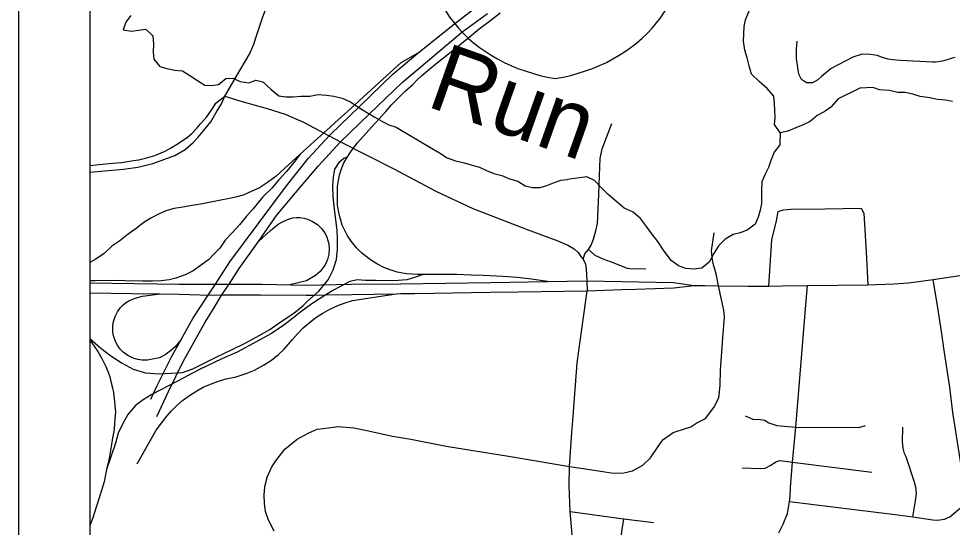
# Model space of a CAD drawing. Extents: x 0 to 34, y 0 to 22.
# Drawn here: x 12.665 to 13.978, y 5.441 to 6.155 of the extents above; entities that cross this region are included whole.
import ezdxf

# ---------------------------------------------------------------- set-up
doc = ezdxf.new("R2010")
doc.units = 0
for name, color, linetype in [('GM_X_City_Street', 7, 'Continuous'), ('GM_X_Corporation', 7, 'Continuous'), ('GM_X_Interchange_Ramps', 7, 'Continuous'), ('GM_X_Interstate_Route', 7, 'Continuous'), ('GM_X_Interstate_Shield', 7, 'Continuous'), ('GM_X_Minor_River', 7, 'Continuous'), ('GM_X_Minor_River_Text', 7, 'Continuous'), ('GM_X_State_Route', 7, 'Continuous'), ('GM_X_US_Route', 7, 'Continuous'), ('SH_Data', 7, 'Continuous')]:
    doc.layers.add(name, color=color, linetype=linetype)

msp = doc.modelspace()

# ---------------------------------------------------------------- linework, layer by layer
at = {"layer": 'GM_X_City_Street'}
msp.add_line((13.7534, 5.5325), (13.8647, 5.5184), dxfattribs=at)
for points in [[(12.9544, 6.0468), (12.9755, 6.0825), (12.9848, 6.0975), (12.9892, 6.1054), (12.9954, 6.1197), (12.9993, 6.1316), (13.0074, 6.1566), (13.0238, 6.2011)], [(13.9819, 6.1008), (13.9778, 6.0999), (13.9659, 6.0963), (13.9586, 6.0949), (13.9544, 6.0945), (13.9505, 6.0945), (13.9046, 6.0969), (13.8939, 6.0976), (13.8878, 6.0985), (13.88, 6.1011), (13.8725, 6.1038), (13.8594, 6.1058), (13.8497, 6.1051), (13.8381, 6.1012), (13.8077, 6.0855), (13.7939, 6.0744), (13.7887, 6.0696), (13.7814, 6.0654), (13.773, 6.0655), (13.7658, 6.0699), (13.7619, 6.0774), (13.7588, 6.0994), (13.7589, 6.1127), (13.7596, 6.124)], [(12.7646, 5.9396), (12.7806, 5.9413), (12.8123, 5.944), (12.8321, 5.947), (12.8534, 5.9518), (12.8704, 5.958), (12.8842, 5.9634), (12.8986, 5.9718), (12.9103, 5.9814), (12.9173, 5.989), (12.9264, 6.0002), (12.9348, 6.0103), (12.9425, 6.0235), (12.9498, 6.0358), (12.9544, 6.0468)], [(12.7646, 5.9492), (12.7913, 5.952), (12.8093, 5.9536), (12.8232, 5.9555), (12.8333, 5.9573), (12.843, 5.9593), (12.8561, 5.9634), (12.8706, 5.9694), (12.8781, 5.9734), (12.8891, 5.98), (12.902, 5.9891), (12.908, 5.9942), (12.9158, 6.0022), (12.9206, 6.0076), (12.9287, 6.0172), (12.9376, 6.0296), (12.9418, 6.0367), (12.9544, 6.0468)], [(12.9544, 6.0468), (12.9771, 6.0397), (13.0144, 6.0293), (13.0396, 6.0211), (13.0653, 6.0099), (13.1012, 5.9909), (13.1101, 5.9861)], [(13.4586, 5.8177), (13.4612, 5.8249), (13.4663, 5.8313), (13.4702, 5.8372), (13.4716, 5.8411), (13.4734, 5.8457), (13.4763, 5.8573), (13.4791, 5.8676), (13.4808, 5.9085), (13.4816, 5.9346), (13.4824, 5.959), (13.4853, 5.9727), (13.494, 5.9946), (13.499, 6.0082)], [(13.1101, 5.9861), (13.1172, 5.9824), (13.1925, 5.9443), (13.2516, 5.9132), (13.3034, 5.8888), (13.3801, 5.8593), (13.4229, 5.8435), (13.4372, 5.8374), (13.4462, 5.8323), (13.4515, 5.827), (13.4556, 5.8215)], [(13.7199, 5.7798), (13.7218, 5.8085), (13.7242, 5.8445), (13.7305, 5.8712), (13.7328, 5.8845), (13.7407, 5.8869), (13.7508, 5.8877), (13.7987, 5.8884), (13.8496, 5.8892), (13.8537, 5.882), (13.8569, 5.8276), (13.8592, 5.7817)], [(13.6492, 5.7803), (13.6461, 5.7946), (13.6437, 5.8036), (13.6415, 5.8115), (13.64, 5.82), (13.6392, 5.8294), (13.6429, 5.8546)], [(13.4556, 5.8215), (13.4586, 5.8177), (13.4618, 5.8103), (13.4629, 5.8037), (13.464, 5.787), (13.4643, 5.7732)], [(13.4663, 5.8313), (13.4749, 5.8231), (13.4863, 5.8178), (13.5018, 5.8122), (13.5167, 5.8062), (13.52, 5.8047), (13.5243, 5.8044), (13.547, 5.8039)], [(13.4397, 5.526), (13.4683, 5.5221), (13.489, 5.5189), (13.5012, 5.5168), (13.5159, 5.5172), (13.5283, 5.5202), (13.5428, 5.5283), (13.5534, 5.5386), (13.5635, 5.5529), (13.5706, 5.5639), (13.5855, 5.574), (13.6027, 5.5795), (13.6104, 5.582), (13.6188, 5.5876), (13.6309, 5.5936), (13.6427, 5.6093), (13.6497, 5.6227), (13.6513, 5.6399), (13.6521, 5.6619), (13.6537, 5.687), (13.6553, 5.7068), (13.6573, 5.7359), (13.6566, 5.7459), (13.6492, 5.7803)], [(13.7338, 5.4329), (13.7401, 5.4451), (13.7463, 5.4604), (13.7491, 5.4768), (13.7499, 5.4839), (13.7503, 5.4968), (13.7534, 5.5325), (13.7577, 5.5815), (13.772, 5.7536), (13.7745, 5.7807)], [(14.0102, 5.4958), (14.002, 5.5019), (13.9972, 5.5071), (13.9938, 5.5119), (13.9918, 5.5187), (13.9787, 5.6019), (13.9745, 5.6379), (13.9663, 5.6927), (13.9636, 5.71), (13.9579, 5.7464), (13.9511, 5.7888)], [(13.4451, 5.6022), (13.4451, 5.6032), (13.4501, 5.6721), (13.4643, 5.7732)], [(13.5638, 4.8429), (13.5518, 4.9196), (13.5394, 5.0228), (13.5335, 5.0511), (13.5283, 5.0648), (13.5128, 5.1064), (13.4939, 5.1627), (13.4835, 5.1909), (13.4739, 5.2251), (13.4632, 5.2698), (13.4577, 5.3026), (13.455, 5.3174), (13.4484, 5.3746), (13.4454, 5.4039), (13.4405, 5.463), (13.4391, 5.4994), (13.4397, 5.526), (13.4427, 5.5741), (13.4451, 5.6022)], [(13.6868, 5.5976), (13.6974, 5.5925), (13.7083, 5.5921), (13.7138, 5.5913), (13.7197, 5.5878), (13.7311, 5.5838), (13.7577, 5.5815)], [(13.0138, 5.5104), (13.0207, 5.5258), (13.0264, 5.534), (13.039, 5.5508), (13.0562, 5.5647), (13.0717, 5.5729), (13.0844, 5.5786), (13.1003, 5.5806), (13.1142, 5.5822), (13.1359, 5.5806), (13.1542, 5.5769), (13.1906, 5.5688), (13.2165, 5.5644), (13.2662, 5.5548), (13.3539, 5.5409), (13.3926, 5.534), (13.4397, 5.526)], [(13.7577, 5.5815), (13.8463, 5.5811), (13.8557, 5.5838)], [(13.9226, 5.4553), (13.9264, 5.4779), (13.9274, 5.4882), (13.9267, 5.4971), (13.9246, 5.504), (13.9133, 5.5397), (13.9109, 5.5443), (13.909, 5.5521), (13.9078, 5.5611), (13.9082, 5.5815)], [(13.6825, 5.5243), (13.7075, 5.5235), (13.7146, 5.5239), (13.722, 5.5278), (13.7307, 5.5333), (13.7358, 5.5345), (13.7534, 5.5325)], [(13.7491, 5.4768), (13.9014, 5.4584), (13.9226, 5.4553), (13.9507, 5.4512), (13.9572, 5.4509), (13.9671, 5.4523), (13.9743, 5.4557), (13.9805, 5.4608), (13.9928, 5.4708), (14.0003, 5.4786), (14.0102, 5.4958), (14.0167, 5.5084), (14.0253, 5.5166), (14.0349, 5.5225), (14.0448, 5.5252), (14.077, 5.5296)], [(13.0138, 5.5104), (13.0103, 5.4977), (13.0094, 5.4858), (13.0101, 5.4744), (13.0116, 5.4633), (13.0154, 5.4515), (13.0235, 5.436)], [(13.4405, 5.463), (13.5158, 5.4526), (13.5575, 5.4477)], [(13.5121, 5.368), (13.5093, 5.3862), (13.509, 5.4028), (13.511, 5.4223), (13.5158, 5.4526)]]:
    msp.add_lwpolyline(points, dxfattribs=at)
at = {"layer": 'GM_X_Corporation'}
for points in [[(12.7646, 9.6504), (12.7646, 4.5526)], [(16.0546, 8.4904), (15.3473, 8.5302), (15.334, 8.5309), (14.9063, 8.5471), (14.6084, 8.5661), (14.4977, 8.5718), (14.2608, 8.5815), (13.795, 8.6047), (13.7169, 8.6042), (13.4613, 8.6292), (13.3525, 8.6386), (13.1948, 8.6507), (13.1161, 8.6564), (13.0467, 8.6615), (12.8988, 8.6726), (12.8448, 8.6761), (12.8296, 8.6783), (12.8119, 8.6756), (12.7953, 8.6676), (12.7646, 8.6719), (12.7646, 3.3841)], [(12.7646, 8.6719), (12.7646, 3.3841)]]:
    msp.add_lwpolyline(points, dxfattribs=at)
at = {"layer": 'GM_X_Interchange_Ramps'}
for points in [[(13.4086, 5.7862), (13.3862, 5.7896), (13.3658, 5.7919), (13.3455, 5.7932), (13.3182, 5.7945), (13.3011, 5.7952), (13.281, 5.7958), (13.2338, 5.7959), (13.2251, 5.7961), (13.21, 5.7968), (13.1972, 5.7994), (13.1857, 5.8031), (13.1784, 5.8057), (13.1692, 5.8103), (13.161, 5.8155), (13.1534, 5.8211), (13.1469, 5.8264), (13.14, 5.8333), (13.1324, 5.8428), (13.1268, 5.8514), (13.1238, 5.857), (13.1199, 5.8655), (13.116, 5.879), (13.1146, 5.8856), (13.1133, 5.8938), (13.113, 5.9037), (13.113, 5.9119), (13.1133, 5.9195), (13.1143, 5.928), (13.116, 5.9362), (13.1186, 5.9444), (13.1222, 5.953), (13.1271, 5.9612), (13.1324, 5.9691), (13.1413, 5.9809), (13.1492, 5.9901), (13.1574, 5.999), (13.1809, 6.0252), (13.1891, 6.0344), (13.1985, 6.0437), (13.209, 6.0539), (13.2189, 6.0631), (13.2251, 6.0694), (13.2317, 6.0756), (13.2402, 6.0826), (13.254, 6.0938), (13.2693, 6.1062), (13.2855, 6.1194), (13.301, 6.1319), (13.3122, 6.1411), (13.3287, 6.1532), (13.3418, 6.1638)], [(13.2259, 6.107), (13.2023, 6.0936), (13.1821, 6.0753), (13.166, 6.0607), (13.149, 6.0452), (13.1265, 6.0248), (13.1146, 6.014), (13.1027, 6.0032), (13.0805, 5.983), (13.0699, 5.9734), (13.0608, 5.9652), (13.0492, 5.9546), (13.0386, 5.945), (13.0267, 5.9342), (13.0148, 5.9254), (13.0035, 5.918), (12.9917, 5.9125), (12.9803, 5.9076), (12.9714, 5.9051), (12.9616, 5.9027), (12.9515, 5.9011), (12.9349, 5.8977), (12.9211, 5.8948), (12.9088, 5.8928), (12.8955, 5.8908), (12.8832, 5.8889), (12.8718, 5.8854), (12.8615, 5.881), (12.8506, 5.8751), (12.8407, 5.8691), (12.8299, 5.8608), (12.8185, 5.8529), (12.8067, 5.8435), (12.7959, 5.8356), (12.785, 5.8257), (12.7732, 5.8174), (12.7646, 5.8129)], [(13.0608, 5.9652), (13.0519, 5.9536), (13.0412, 5.9408), (13.0305, 5.9289), (13.0207, 5.9174), (13.0083, 5.9051), (12.994, 5.8878), (12.9853, 5.8779), (12.9751, 5.866), (12.9648, 5.8545), (12.9553, 5.8442), (12.9475, 5.8331), (12.9397, 5.8249), (12.9315, 5.8167), (12.9216, 5.8097), (12.9101, 5.8011), (12.8986, 5.7953), (12.8859, 5.7908), (12.8764, 5.7887), (12.8653, 5.7871), (12.853, 5.7867), (12.8386, 5.7867), (12.8139, 5.7871), (12.7967, 5.7875), (12.7724, 5.7871), (12.7646, 5.7869)], [(12.7646, 5.7059), (12.7801, 5.6926), (12.7944, 5.6817), (12.8102, 5.6714), (12.8259, 5.663), (12.8432, 5.658), (12.8624, 5.6566), (12.895, 5.6585), (12.9098, 5.6635), (12.931, 5.6743), (12.9443, 5.6807), (12.964, 5.6901), (12.9843, 5.7), (13.003, 5.7103), (13.0178, 5.7187), (13.0326, 5.7291), (13.0518, 5.7419), (13.0642, 5.7518), (13.0711, 5.7587), (13.0869, 5.7725), (13.1002, 5.7887), (13.1071, 5.8026), (13.1115, 5.8169), (13.113, 5.8317), (13.113, 5.845), (13.1125, 5.8583), (13.111, 5.8726), (13.109, 5.8884), (13.1071, 5.9051), (13.1066, 5.9204), (13.1076, 5.9328), (13.1095, 5.9441), (13.1164, 5.955), (13.1219, 5.9594), (13.1271, 5.9612)], [(13.0018, 5.8424), (13.0132, 5.8526), (13.0191, 5.8576), (13.0245, 5.8626), (13.0298, 5.8667), (13.0356, 5.87), (13.043, 5.8733), (13.0503, 5.8756), (13.0553, 5.8761), (13.0603, 5.8759), (13.0662, 5.8751), (13.0721, 5.8734), (13.079, 5.8702), (13.0848, 5.8662), (13.0905, 5.8607), (13.0951, 5.8545), (13.0981, 5.8485), (13.1008, 5.8393), (13.1015, 5.832), (13.1009, 5.8245), (13.0992, 5.8173), (13.0958, 5.8097), (13.0889, 5.8004), (13.0821, 5.7946), (13.0693, 5.7872), (13.0462, 5.7816)], [(13.2338, 5.7959), (13.2215, 5.7917), (13.2106, 5.7887), (13.1983, 5.7878), (13.1825, 5.7873), (13.1668, 5.7878), (13.1524, 5.7878), (13.1411, 5.7883), (13.1303, 5.7863), (13.1066, 5.7735), (13.0839, 5.7596), (13.075, 5.7532), (13.0617, 5.7434), (13.0499, 5.734), (13.0356, 5.7232), (13.0193, 5.7128), (12.9996, 5.7019), (12.9719, 5.6871), (12.9502, 5.6773), (12.9192, 5.6625), (12.8881, 5.6462), (12.8521, 5.6275), (12.8398, 5.6201), (12.8289, 5.6117), (12.8181, 5.5994), (12.8116, 5.5875), (12.8047, 5.5732), (12.8008, 5.5589), (12.788, 5.5222)], [(12.8933, 5.7047), (12.8846, 5.6945), (12.878, 5.6889), (12.8705, 5.6833), (12.8626, 5.679), (12.8527, 5.6769), (12.846, 5.6757), (12.8377, 5.6756), (12.8323, 5.6764), (12.8257, 5.6783), (12.8182, 5.682), (12.8118, 5.6867), (12.8074, 5.6913), (12.804, 5.6959), (12.8007, 5.7019), (12.7983, 5.7086), (12.7972, 5.7147), (12.797, 5.7237), (12.7979, 5.73), (12.8002, 5.7371), (12.8036, 5.7437), (12.8079, 5.7496), (12.8111, 5.7528), (12.8149, 5.756), (12.8198, 5.7592), (12.8284, 5.7629), (12.8386, 5.7655), (12.8494, 5.7671), (12.8636, 5.7687)], [(12.8313, 5.5298), (12.8582, 5.5774), (12.8731, 5.5968), (12.8796, 5.6043), (12.887, 5.6117), (12.8952, 5.6188), (12.9051, 5.6262), (12.9151, 5.6325), (12.9243, 5.6375), (12.9346, 5.6421), (12.9471, 5.6466), (12.9567, 5.6492), (12.9707, 5.6524), (12.9848, 5.6568), (12.9963, 5.6616), (13.0091, 5.6684), (13.0202, 5.6758), (13.0302, 5.6838), (13.0381, 5.6913), (13.0498, 5.7048), (13.0567, 5.7128), (13.0649, 5.721), (13.0762, 5.7306), (13.0841, 5.7364), (13.0924, 5.7417), (13.1024, 5.7472), (13.1138, 5.7524), (13.1224, 5.7556), (13.1343, 5.7594), (13.1955, 5.769)], [(12.7646, 5.7038), (12.7663, 5.7017), (12.7709, 5.6954), (12.7758, 5.6876), (12.782, 5.677), (12.787, 5.6668), (12.7906, 5.6589), (12.7929, 5.652), (12.7949, 5.6438), (12.7968, 5.6366), (12.7978, 5.6303), (12.7991, 5.6218), (12.7998, 5.6126), (12.8008, 5.6027), (12.8001, 5.5935), (12.7995, 5.585), (12.7985, 5.5748), (12.7968, 5.5666), (12.7952, 5.5573), (12.7939, 5.5488), (12.7922, 5.5402), (12.7903, 5.531), (12.788, 5.5222), (12.7849, 5.5046), (12.7787, 5.485), (12.7737, 5.4692), (12.7688, 5.4539), (12.7646, 5.4431)]]:
    msp.add_lwpolyline(points, dxfattribs=at)
at = {"layer": 'GM_X_Interstate_Route'}
for points in [[(12.8505, 5.6209), (12.8595, 5.6402), (12.8795, 5.6802), (12.8933, 5.7047), (12.9098, 5.7342), (12.9314, 5.7671), (12.9414, 5.7825), (12.9619, 5.8139), (13.0415, 5.9207), (13.0724, 5.9594), (13.1012, 5.9909), (13.1036, 5.9934), (13.1441, 6.0322), (13.191, 6.0774), (13.2259, 6.107), (13.2758, 6.1466), (13.3106, 6.1737)], [(12.9386, 5.7478), (12.9506, 5.7672), (12.9605, 5.7824), (12.9748, 5.8043), (13.0018, 5.8424), (13.0274, 5.8787), (13.0539, 5.9109), (13.086, 5.9484), (13.1172, 5.9824), (13.1577, 6.0212), (13.2046, 6.0664), (13.2395, 6.096), (13.2882, 6.1364), (13.3242, 6.1627)], [(12.859, 5.5964), (12.8752, 5.6315), (12.896, 5.6736), (12.9272, 5.7292), (12.9386, 5.7478)]]:
    msp.add_lwpolyline(points, dxfattribs=at)
at = {"layer": 'GM_X_Interstate_Shield'}
for centre, start_param, end_param in [((13.4639, 6.2453), 2.911027, 4.511031), ((13.3751, 6.2453), 4.913747, 6.513751)]:
    msp.add_ellipse(centre, major_axis=(0.2219, 0), ratio=0.8, start_param=start_param, end_param=end_param, dxfattribs=at)
at = {"layer": 'GM_X_Minor_River'}
for points in [[(12.8226, 6.1601), (12.8153, 6.1504), (12.8114, 6.1398), (12.8235, 6.1377), (12.833, 6.1391), (12.8436, 6.1409), (12.8533, 6.1313), (12.8543, 6.1195), (12.8538, 6.1085), (12.8548, 6.0986), (12.863, 6.0882), (12.8732, 6.0854), (12.8845, 6.083), (12.8951, 6.0821), (12.9056, 6.0755), (12.9162, 6.0685), (12.9263, 6.0619), (12.9362, 6.0614), (12.9456, 6.0632), (12.956, 6.0714), (12.9658, 6.072), (12.976, 6.0674), (12.9885, 6.0653), (12.9984, 6.069), (13.0082, 6.0666), (13.0198, 6.0561), (13.0307, 6.0469), (13.0405, 6.0456), (13.0507, 6.0455), (13.0614, 6.0465), (13.0742, 6.0467), (13.0853, 6.0488)], [(13.9783, 6.039), (13.9685, 6.0411), (13.9571, 6.042), (13.9462, 6.0441), (13.9329, 6.0461), (13.9224, 6.0493), (13.9118, 6.0518), (13.9012, 6.0519), (13.8898, 6.0544), (13.8758, 6.0553), (13.866, 6.0589), (13.8478, 6.058), (13.8375, 6.0529), (13.8268, 6.0473), (13.8173, 6.0429), (13.8073, 6.0313), (13.7977, 6.0246), (13.7878, 6.0194), (13.7782, 6.0108), (13.7683, 6.0064), (13.758, 6.002), (13.7465, 5.9972), (13.7359, 5.9951), (13.7277, 6.007), (13.7286, 6.0165), (13.7284, 6.026), (13.7277, 6.0366), (13.7271, 6.0465), (13.7174, 6.0573), (13.7062, 6.0674), (13.6957, 6.0774), (13.6924, 6.0892), (13.6896, 6.1003), (13.6863, 6.111), (13.6842, 6.1239), (13.6847, 6.1338), (13.6852, 6.1444), (13.6869, 6.1539), (13.6923, 6.1667)], [(13.0853, 6.0488), (13.0977, 6.0479), (13.108, 6.0466), (13.1197, 6.0438), (13.1313, 6.0387), (13.1419, 6.0318), (13.1531, 6.0244), (13.1655, 6.017), (13.1757, 6.0116), (13.1855, 6.0065), (13.1957, 6.0029), (13.2073, 5.996), (13.2235, 5.9866), (13.2453, 5.9734), (13.2566, 5.9668), (13.2675, 5.9598), (13.2792, 5.9559), (13.2913, 5.9527), (13.3026, 5.9495), (13.3128, 5.9467), (13.3226, 5.942), (13.3331, 5.9381), (13.3441, 5.9349), (13.355, 5.9306), (13.3667, 5.927), (13.3772, 5.9208), (13.387, 5.9184), (13.398, 5.9182), (13.4075, 5.9212), (13.4171, 5.9248), (13.4273, 5.9285), (13.4367, 5.9293)], [(13.7359, 5.9951), (13.7353, 5.9784), (13.7272, 5.9679), (13.7225, 5.9562), (13.7193, 5.9463), (13.7143, 5.9362), (13.71, 5.9263), (13.7094, 5.9146), (13.7096, 5.896), (13.7079, 5.8865), (13.7051, 5.8766), (13.7005, 5.8668), (13.6893, 5.8583), (13.6798, 5.8546), (13.6699, 5.8521), (13.6585, 5.8458), (13.6492, 5.8361), (13.6423, 5.8255), (13.6361, 5.8135), (13.6257, 5.8049), (13.6143, 5.8035), (13.603, 5.8044), (13.5928, 5.8084), (13.5826, 5.8158), (13.5715, 5.83), (13.5637, 5.8423), (13.5555, 5.853), (13.548, 5.8634), (13.5395, 5.8745), (13.529, 5.8834), (13.5162, 5.8893), (13.5064, 5.8978), (13.4937, 5.9083), (13.4847, 5.9179), (13.4746, 5.9279), (13.4641, 5.9334), (13.4367, 5.9293)]]:
    msp.add_lwpolyline(points, dxfattribs=at)
at = {"layer": 'GM_X_State_Route'}
for p, q in [((13.9511, 5.7888), (13.9978, 5.7959)), ((13.6297, 5.7804), (13.6492, 5.7803)), ((13.7097, 5.7797), (13.7199, 5.7798)), ((13.7745, 5.7807), (13.8592, 5.7817)), ((13.9408, 5.7875), (13.9511, 5.7888)), ((13.3672, 5.7718), (13.4643, 5.7732)), ((13.4643, 5.7732), (13.5131, 5.7749)), ((13.5131, 5.7749), (13.5326, 5.7755))]:
    msp.add_line(p, q, dxfattribs=at)
for points in [[(13.5326, 5.7755), (13.5862, 5.7774), (13.615, 5.7805), (13.6297, 5.7804)], [(13.6492, 5.7803), (13.6902, 5.7796), (13.7097, 5.7797)], [(13.7199, 5.7798), (13.7392, 5.7803), (13.7745, 5.7807)], [(13.8592, 5.7817), (13.8956, 5.7829), (13.9162, 5.7845), (13.9408, 5.7875)], [(12.7646, 5.7701), (12.8234, 5.7695), (12.8636, 5.7687)], [(12.8636, 5.7687), (12.8903, 5.7682), (12.9195, 5.7674)], [(12.9195, 5.7674), (12.9314, 5.7671), (12.9506, 5.7672), (13.0049, 5.7673)], [(13.0049, 5.7673), (13.0691, 5.7669), (13.0807, 5.7671), (13.0966, 5.7674), (13.1338, 5.768)], [(13.1338, 5.768), (13.1955, 5.769), (13.2022, 5.7691), (13.2216, 5.7694)], [(13.2216, 5.7694), (13.3283, 5.7713), (13.3672, 5.7718)]]:
    msp.add_lwpolyline(points, dxfattribs=at)
at = {"layer": 'GM_X_US_Route'}
for p, q in [((13.9511, 5.7888), (13.9978, 5.7959)), ((13.6297, 5.7804), (13.6492, 5.7803)), ((13.7097, 5.7797), (13.7199, 5.7798)), ((13.7745, 5.7807), (13.8592, 5.7817)), ((13.9408, 5.7875), (13.9511, 5.7888)), ((13.3672, 5.7718), (13.4643, 5.7732)), ((13.4643, 5.7732), (13.5131, 5.7749)), ((13.5131, 5.7749), (13.5326, 5.7755))]:
    msp.add_line(p, q, dxfattribs=at)
for points in [[(12.7646, 5.7845), (12.8902, 5.7825), (12.9414, 5.7825), (12.9605, 5.7824), (13.0067, 5.7824), (13.0692, 5.7812), (13.1324, 5.7822), (13.2024, 5.7827), (13.3286, 5.7849), (13.4086, 5.7862), (13.464, 5.787)], [(13.464, 5.787), (13.5856, 5.7849), (13.615, 5.7805)], [(13.5326, 5.7755), (13.5862, 5.7774), (13.615, 5.7805), (13.6297, 5.7804)], [(13.6492, 5.7803), (13.6902, 5.7796), (13.7097, 5.7797)], [(13.7199, 5.7798), (13.7392, 5.7803), (13.7745, 5.7807)], [(13.8592, 5.7817), (13.8956, 5.7829), (13.9162, 5.7845), (13.9408, 5.7875)], [(12.7646, 5.7701), (12.8234, 5.7695), (12.8636, 5.7687)], [(12.8636, 5.7687), (12.8903, 5.7682), (12.9195, 5.7674)], [(12.9195, 5.7674), (12.9314, 5.7671), (12.9506, 5.7672), (13.0049, 5.7673)], [(13.0049, 5.7673), (13.0691, 5.7669), (13.0807, 5.7671), (13.0966, 5.7674), (13.1338, 5.768)], [(13.1338, 5.768), (13.1955, 5.769), (13.2022, 5.7691), (13.2216, 5.7694)], [(13.2216, 5.7694), (13.3283, 5.7713), (13.3672, 5.7718)]]:
    msp.add_lwpolyline(points, dxfattribs=at)
at = {"layer": 'SH_Data'}
for p, q in [((12.6646, 10.2841), (12.6646, 3.2841)), ((12.7646, 10.1841), (12.7646, 3.3841))]:
    msp.add_line(p, q, dxfattribs=at)

# ---------------------------------------------------------------- texts
at = {"layer": 'GM_X_Minor_River_Text'}
msp.add_text('Run', height=0.0947, rotation=340.5067, dxfattribs=at).set_placement((13.236, 6.0332))

doc.saveas('drawing.dxf')
